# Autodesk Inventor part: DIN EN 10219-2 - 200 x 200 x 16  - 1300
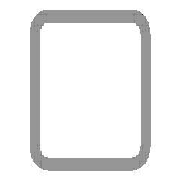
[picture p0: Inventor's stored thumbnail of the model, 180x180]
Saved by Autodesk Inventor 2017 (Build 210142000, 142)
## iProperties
Created: 2017-11
Part Number: DIN EN 10219-2 - 200 x 200 x 16  - 1300
Material: Steel, Mild
Description: Cold formed welded structural hollow sections of non-alloy and fine grain structural steel
Document SubType Name: Modeling
Standard: DIN
Designer: iusti
Standard Revision: 2006-07
Standards Organization: DIN
Language: en-US
Size Designation: 200 x 200 x 16
Categories: <MemberInstance><Categories><Category DisplayName="Structural Shapes" InternalName="089c4875-fa83-4c05-b084-43b9cc11f5ed" Mnemonic="GRDR"><CategoryParameter Dis
Stock Number: 200 x 200 x 16
Mass: 108961 g
Surface Area: 17564.1 cm^2
Volume: 13880.4 cm^3
Density: 7.85 g/cm^3
Appearance: Semi-Polished
_CCFamilyMember: 103
_CCFamilyDisplayName: DIN EN 10219-2 (Square Hollow Section - Cold Formed) - Cold formed welded structural hollow sections of non-alloy and fine grain structural steel
_FrameMemberDoc: Frame Member File
_Version: 15.0.0
_GetPNFromCC: 1
G_L: 1300.000 mm
G_W: 200.000 mm
G_H: 200.000 mm
+25324788-8590-4B72-A89D-365C3D99059D+CUTDETAIL1: Cut
+F0281C93-BF98-4FCA-A581-8417B7D640E2+CUTDETAIL2: Cut
IsCustomPart: 1
Author: iusti
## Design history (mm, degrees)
node "Start plane"
node "End plane"
sketch "Sketch"
  geometry: L1 (-100, -52)-(-100, 52); L2 (-52, 100)-(52, 100); L3 (100, 52)-(100, -52); L4 (52, -100)-(-52, -100); L5 (-52, 84)-(52, 84); L6 (84, 52)-(84, -52); L7 (52, -84)-(-52, -84); L8 (-84, -52)-(-84, 52); L9 (0, 153.918)-(0, -153.918) reference; L10 (-153.918, 0)-(153.918, 0) reference; A1 r 48 centre (-52, -52) between (-100, -52) and (-52, -100); A2 r 48 centre (-52, 52) between (-52, 100) and (-100, 52); A3 r 48 centre (52, 52) between (100, 52) and (52, 100); A4 r 48 centre (52, -52) between (52, -100) and (100, -52); A5 r 32 centre (-52, 52) between (-52, 84) and (-84, 52); A6 r 32 centre (52, 52) between (84, 52) and (52, 84); A7 r 32 centre (52, -52) between (52, -84) and (84, -52); A8 r 32 centre (-52, -52) between (-84, -52) and (-52, -84)
  constraints: 16 end point, 16 point on circle, 8 centre point, 8 tangent, 4 parallel, 3 equal radius, 2 perpendicular, 7 other
  dimensions: "d7" = 48 radius of A1 (= G_IR); "d10" = 200 distance between parallel lines of L2 L4 (= G_H); "d11" = 200 distance between parallel lines of L1 L3 (= G_W); "d12" = 16 distance between parallel lines of L3 L6 (= G_T); "d15" = 100 distance between parallel lines of L2 L10 (= 0.5 x d10); "d16" = 100 distance between parallel lines of L9 L3 (= 0.5 x d11)
extrude "Body" new body sketch "Sketch" stored distance "d3" = 1300 (= G_L); taper "d4" = 0 deg
node "Driven Length"
  sketch "Sketch3"
    geometry: L1 (0, 0)-(10, 0) reference
    constraints: 2 end point, 1 horizontal
  workplane "Work Plane3"
  sketch "Sketch4"
    geometry: L1 (-2, 100)-(12, 100) reference; L2 (-2, 1400)-(12, 1400) reference
    dimensions: "d18" = 1300 distance between parallel lines of L1 L2 (derived)
workplane "Work Plane4"
split "Split1"
workplane "Work Plane5"
split "Split2"
body "Solid1"
other parameters: "G_W" = 200 [user parameter; used in 1 equation term], "G_H" = 200 [user parameter; used in 1 equation term], "G_T" = 16 [user parameter; used in 1 equation term], "G_IR" = 48 [user parameter; used in 1 equation term], "G_L" = 1300 (= d18) [user parameter; used in 1 equation term], "d17" = 90 deg
